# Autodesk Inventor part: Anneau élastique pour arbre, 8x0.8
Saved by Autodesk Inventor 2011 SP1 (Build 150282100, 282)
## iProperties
Created: 2010-12
Part Number: Anneau élastique pour arbre, 8x0.8
Document SubType Name: Modeling
Designer: eric
Density: 1 g/cm^3
Mass: 0.0249212 g
Surface Area: 1.07599 cm^2
Volume: 0.0249212 cm^3
Author: eric
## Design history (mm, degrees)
feature "Base1"
node "Solide1"
node "Corps solides"
node "Corps surfaciques"
